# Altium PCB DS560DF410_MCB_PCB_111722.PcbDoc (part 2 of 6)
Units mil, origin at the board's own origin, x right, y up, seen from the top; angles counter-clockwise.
Board outline 5500 x 5000 mil, 6 copper layers (Top Layer, L2_GND1, L3_SIG1, L4_PWR1, L5_GND2, Bottom Layer), stack 61.748 mil thick; 297 components, 231 nets, 1236 pads, 998 vias.
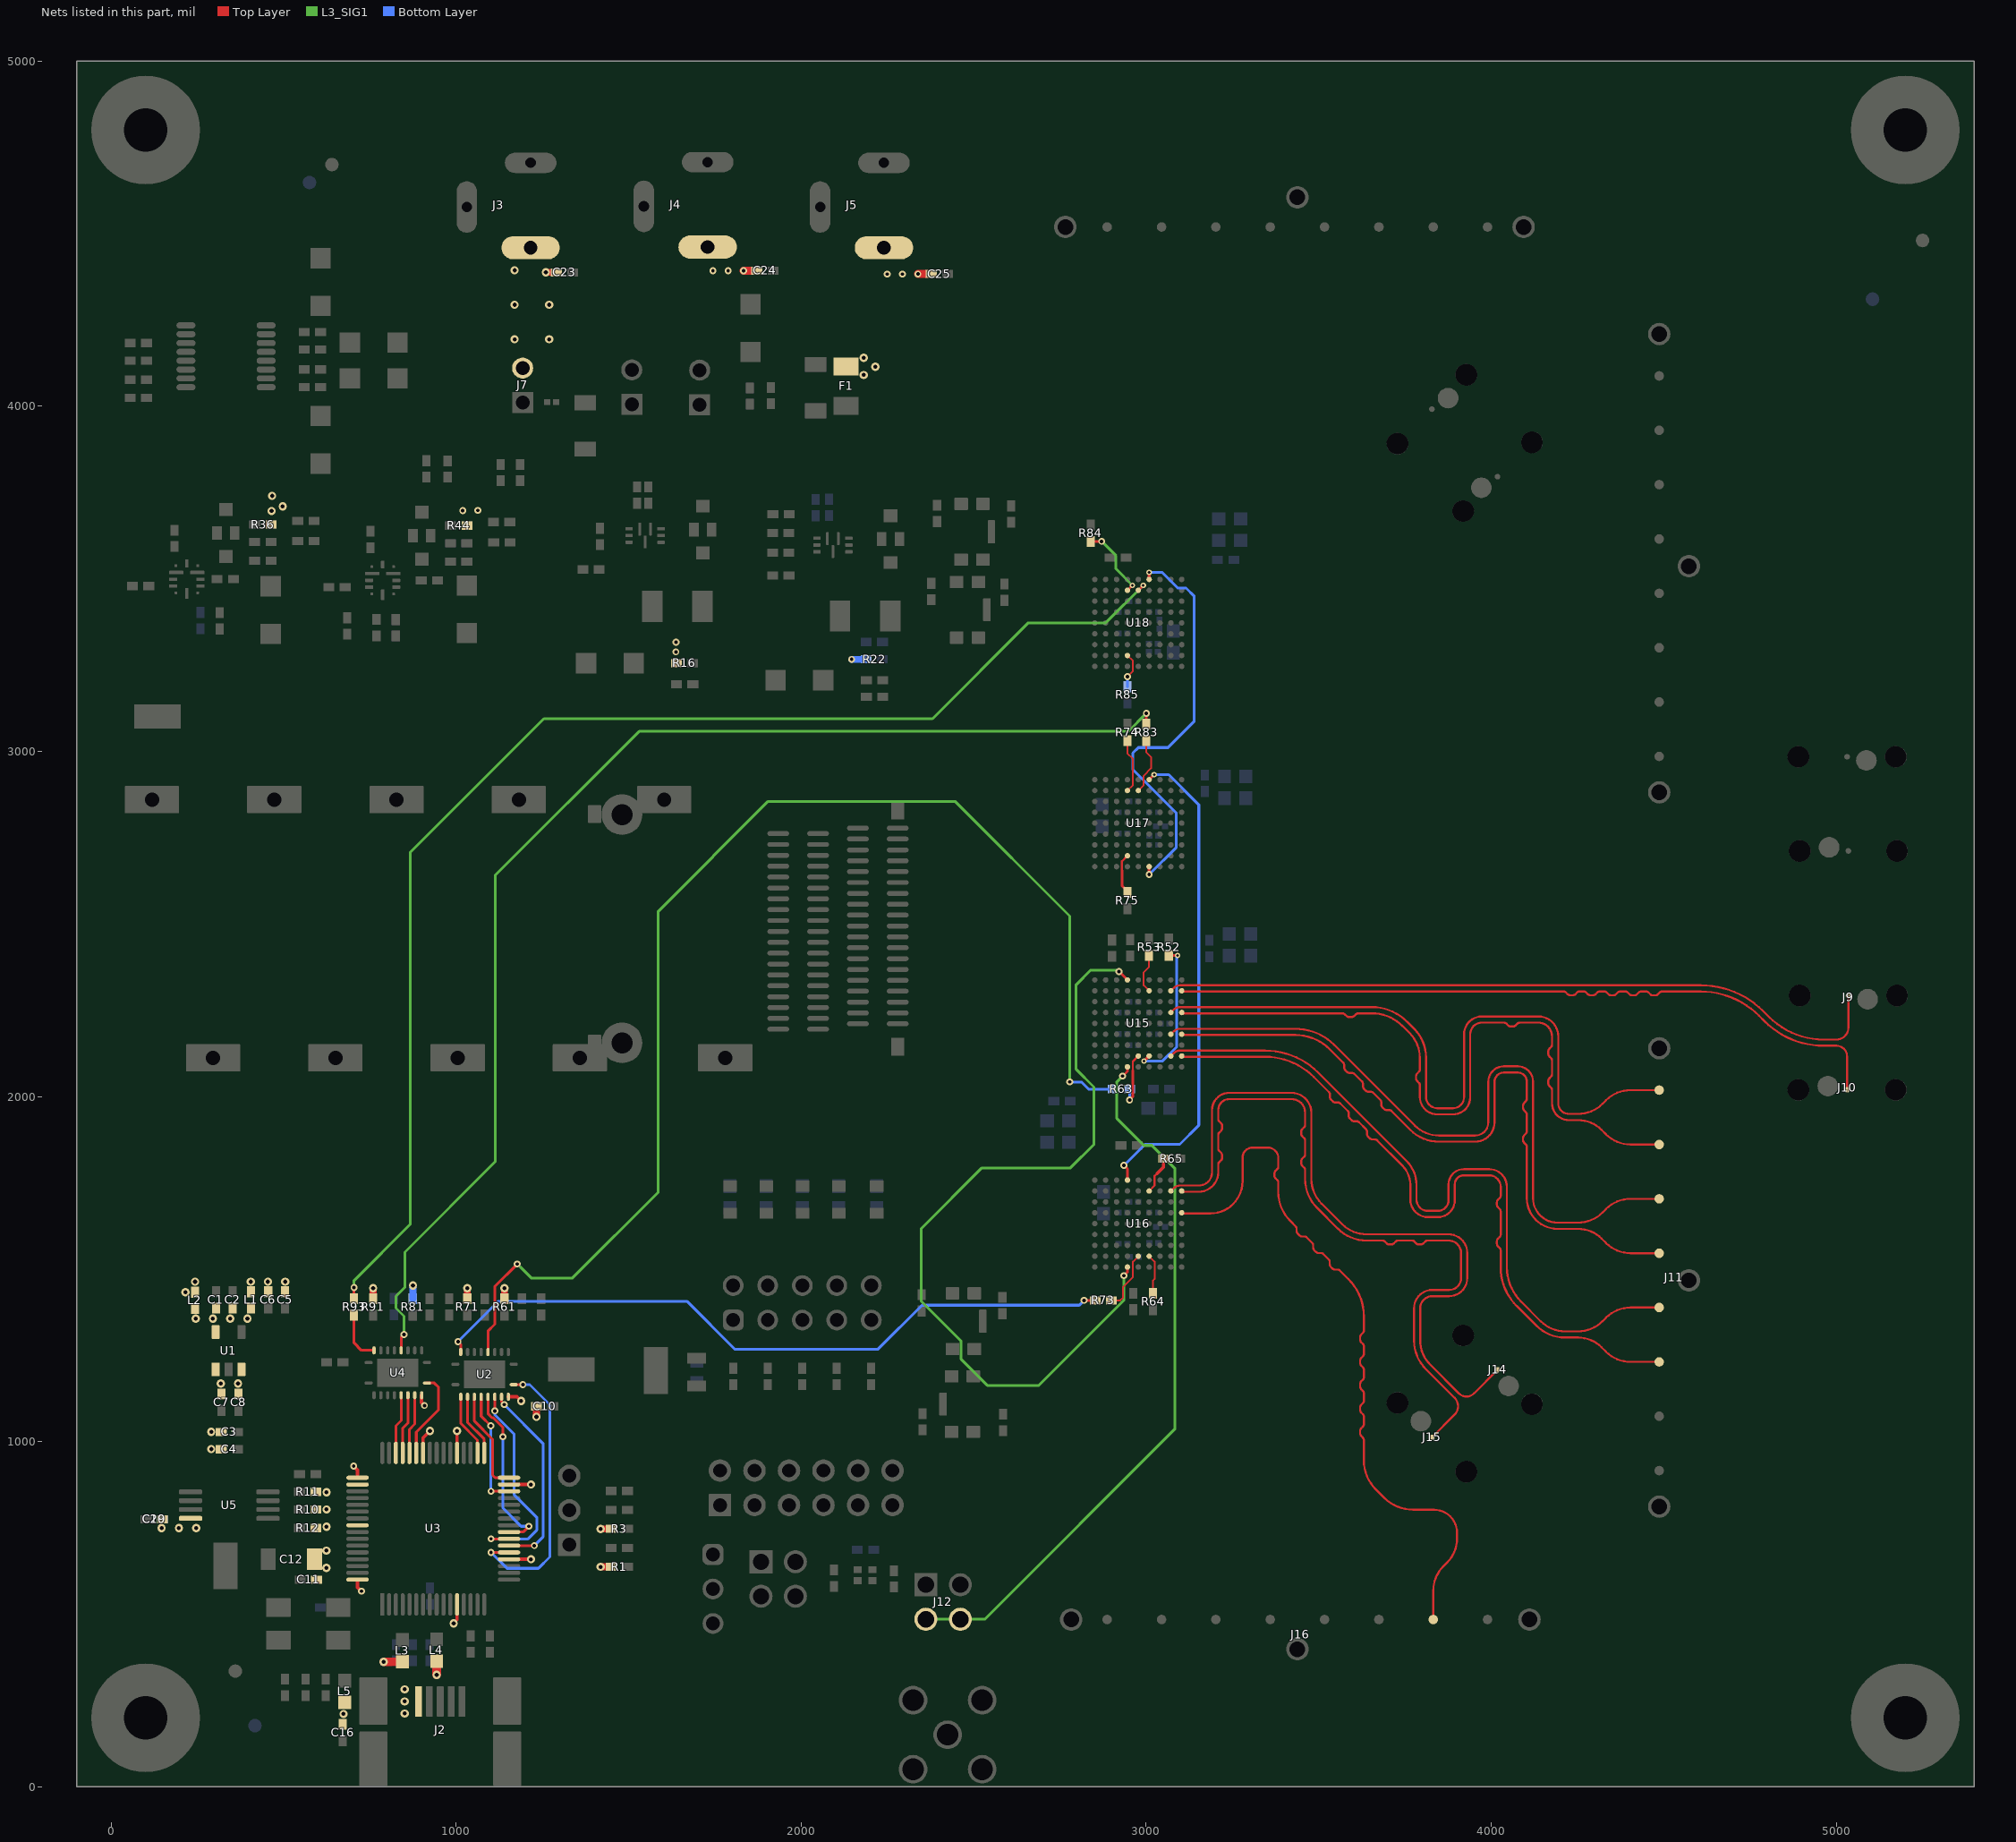
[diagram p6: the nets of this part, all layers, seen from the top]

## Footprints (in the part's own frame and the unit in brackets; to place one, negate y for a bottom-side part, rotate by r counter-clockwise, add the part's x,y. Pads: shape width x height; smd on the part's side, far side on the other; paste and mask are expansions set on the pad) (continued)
SAMTEC_SMA-J-P-H-ST-TH1 [mm] "TH, 5-Leads, Body 7x7mm"
  round 2.1 hole 1.6: 1(0,0) 2(-2.54,2.54) 3(2.54,2.54) 4(2.54,-2.54) 5(-2.54,-2.54)
  silkscreen extent -3.5,-3.5 3.5,3.5, body extent -3.5,-3.5 3.5,3.5, height 9.55
Samtec_TSW-103-08-x-S [mm] "Header, 2.54mm, 3x1, TH"
  rrect50% 1.53x1.53 hole 1.02: 1(-2.54,0)
  round 1.53 hole 1.02: 2(0,0) 3(2.54,0)
  body extent -3.94,-1.27 3.81,1.27, height 8.38
SAMTEC_TSW-105-08-X-D [mm] "Header, 2.54mm, 5x2, TH"
  rrect50% 1.53x1.53 hole 1.02: 1(-1.27,5.08)
  round 1.53 hole 1.02: 2(1.27,5.08) 3(-1.27,2.54) 4(1.27,2.54) 5(-1.27,0) 6(1.27,0) 7(-1.27,-2.54) 8(1.27,-2.54) 9(-1.27,-5.08) 10(1.27,-5.08)
  silkscreen extent -2.54,-6.35 2.54,7.59, body extent -2.54,-6.35 2.54,6.35, height 8.38
SPC02SYAN [mil] "SULLINS"
  round 1 on Mech3: 0(0,0)
  body extent -98,-47 99,47, height 366
Sullins_PxC02DAAN [mm] "Header, 2.54mm, 2x2, TH"
  rect 1.7x1.7 hole 1.2: 1(-1.27,1.27)
  round 1.7 hole 1.2: 2(1.27,1.27) 3(-1.27,-1.27) 4(1.27,-1.27)
  silkscreen extent -2.61,-2.8 2.61,3.2, body extent -2.61,-2.8 2.61,2.8, height 8.58
SW_KMR211GLFS [mm] "SMD. 5-Leads. Body 4.2x2.8mm"
  rrect11% 0.9x1 smd: 1(-2.05,0.8) 2(2.05,0.8) 3(-2.05,-0.8) 4(2.05,-0.8)
  rrect18% 1.7x0.55 smd: 5(0,-1.425)
  silkscreen extent -1.3,1.4 1.3,1.7, body extent -2.3,-1.4 2.3,1.4, height 1.92
Testpoint_Keystone_Miniature [mil] "Miniature SMT test point"
  rect 135x70 smd: 1(0,0)
  silkscreen extent -78,-46 78,45, body extent -52,-20 52,20, height 61
TSSOP-8 [mm] "TSSOP, 8-Leads, Body 3.1x4.5mm (max), Pitch 0.65mm, IPC Medium Density"
  rrect50% 1.7x0.35 smd: 1(-2.85,0.975) 2(-2.85,0.325) 3(-2.85,-0.325) 4(-2.85,-0.975) 5(2.85,-0.975) 6(2.85,-0.325) 7(2.85,0.325) 8(2.85,0.975)
  silkscreen extent -2.98,-1.55 1.6,1.82, body extent -3.2,-1.55 3.2,1.55, height 1.07
TSW-106-07-G-D [mm] "Samtec 100mil, 2x6, 230 mil above insulator"
  rrect6% 1.65x1.65 hole 1.016: 1(-6.35,-1.27)
  round 1.65 hole 1.016: 2(-6.35,1.27) 3(-3.81,-1.27) 4(-3.81,1.27) 5(-1.27,-1.27) 6(-1.27,1.27) 7(1.27,-1.27) 8(1.27,1.27) 9(3.81,-1.27) 10(3.81,1.27) 11(6.35,-1.27) 12(6.35,1.27)
  silkscreen extent -8.64,-2.54 7.62,2.54, body extent -7.62,-2.54 7.62,2.54, height 8.38
WEEE_Minimum [mil] "WEEElie bin"
  silkscreen extent -95,-172 99,104

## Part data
C1 C3 C5 C7 C18: library part CMP-0006268-2, "CAP, CERM, 4.7 uF, 10 V, +/- 10%, X5R, 0402", Cap_Case=0402_065, Manufacturer=TDK, Supplier Part Number 1=445-13820-1-ND, TempCo=X5R, Tolerance_%=10%, Value1="0.003417 ohm", Value2=10V, ValueDisplayed=4.7uF
C2 C4 C6 C8 C9 C10 C13 C17 C19 C20 C53: library part CMP-0860188-1, "CAP, CERM, 0.1 µF, 16 V,+/- 10%, X7R, 0402", Cap_Case=0402, Manufacturer="Taiyo Yuden", TempCo=X7R, Tolerance_%=10%, Value2=16V, ValueDisplayed=0.1µF
C11 C30 C32 C33 C36 C37 C40 C41 C45 C46: library part CMP-0084009-1, "CAP, CERM, 10 µF, 10 V,+/- 20%, X5R, 0402", Cap_Case=0402, Manufacturer="Samsung Electro-Mechanics", Supplier Part Number 1=1276-6830-6-ND, TempCo=X5R, Tolerance_%=20%, Value1="0.001 ohm", Value2=10V, ValueDisplayed=10µF
C12 C27: library part CMP-0008649-2, "CAP, CERM, 100 uF, 10 V, +/- 20%, X5R, 1206_190", Cap_Case=1206_190, Manufacturer=TDK, Supplier Part Number 1=445-6007-1-ND, TempCo=X5R, Tolerance_%=20%, Value1="0.002838 ohm", Value2=10V, ValueDisplayed=100uF
C14 C15: library part CMP-0006439-2, "CAP, CERM, 22 pF, 50 V, +/- 5%, C0G/NP0, 0402", Cap_Case=0402, Manufacturer=MuRata, Supplier Part Number 1=81-GRM1555C1H220JA1D, TempCo=C0G/NP0, Tolerance_%=5%, Value1=Unknown, Value2=50V, ValueDisplayed=22pF
C16: library part CMP-0006590-2, "CAP, CERM, 0.01 uF, 16 V, +/- 10%, X5R, 0402", Cap_Case=0402, Manufacturer=MuRata, Supplier Part Number 1=GRM155R61C103KA01D-ND, TempCo=X5R, Tolerance_%=10%, Value1=Unknown, Value2=16V, ValueDisplayed=0.01uF
C21 C22: library part CMP-0006365-2, "CAP, CERM, 27 pF, 50 V, +/- 5%, C0G/NP0, 0402", Cap_Case=0402, Manufacturer=MuRata, TempCo=C0G/NP0, Tolerance_%=5%, Value1=Unknown, Value2=50V, ValueDisplayed=27pF
C23 C24 C25 C42 C47: library part CMP-0006347-2, "CAP, CERM, 1 uF, 16 V, +/- 10%, X5R, 0402", Cap_Case=0402, Manufacturer="Taiyo Yuden", Supplier Part Number 1=587-3709-2-ND, TempCo=X5R, Tolerance_%=10%, Value1=Unknown, Value2=16V, ValueDisplayed=1uF
C26: library part CMP-0009013-2, "CAP, CERM, 47 uF, 10 V, +/- 10%, X5R, AEC-Q200 Grade 1, 1206", Cap_Case=1206, Manufacturer=MuRata, Supplier Part Number 1=490-12438-1-ND, TempCo=X5R, Tolerance_%=10%, Value1=Unknown, Value2=10V, ValueDisplayed=47uF
C28 C29 C34 C35 C38 C39: library part CMP-0006545-2, "CAP, CERM, 22 uF, 6.3 V, +/- 20%, X5R, 0402", Cap_Case=0402, Manufacturer=MuRata, TempCo=X5R, Tolerance_%=20%, Value1=Unknown, Value2=6.3V, ValueDisplayed=22uF
C31: library part CMP-0008932-2, "CAP, CERM, 220 uF, 4 V, +/- 20%, X5R, 1206_190", Cap_Case=1206, Manufacturer=MuRata, Supplier Part Number 1=490-9774-1-ND, TempCo=X5R, Tolerance_%=20%, Value1=Unknown, Value2=4V, ValueDisplayed=220uF
C43 C44 C48 C49: library part CMP-0006659-2, "CAP, CERM, 0.1 uF, 25 V, +/- 10%, X7R, 0402", Cap_Case=0402, Manufacturer=MuRata, Supplier Part Number 1=490-10698-1-ND, TempCo=X7R, Tolerance_%=10%, Value1=Unknown, Value2=25V, ValueDisplayed=0.1uF
C50 C51 C52 C56 C60 C62 C63 C64 C67 C71 C73 C74 C75 C78 C82 C84 C85 C86 C89 C93: library part CMP-0009670-3, "CAP, CERM, 0.1 uF, 16 V, +/- 10%, X5R, 0201", Cap_Case=0201, Manufacturer=MuRata, Supplier Part Number 1=490-10387-1-ND, TempCo=X5R, Tolerance_%=10%, Value1=Unknown, Value2=16V, ValueDisplayed=0.1uF
C54 C59 C65 C70 C76 C81 C87 C92: library part CMP-0086060-1, "CAP, CERM, 0.01 µF, 25 V,+/- 10%, X5R, 0201", Cap_Case=0201, Manufacturer=MuRata, TempCo=X5R, Tolerance_%=10%, Value2=25V, ValueDisplayed=0.01µF
C55 C66 C77 C88: library part CMP-0860563-1, "CAP, CERM, 0.22 µF, 16 V,+/- 10%, X7R, 0402", Cap_Case=0402, Manufacturer="Samsung Electro-Mechanics", TempCo=X7R, Tolerance_%=10%, Value2=16V, ValueDisplayed=0.22µF
C57 C58 C61 C68 C69 C72 C79 C80 C83 C90 C91 C94: library part CMP-0007335-5, "CAP, CERM, 1 uF, 16 V, +/- 10%, X5R, 0603", Cap_Case=0603, Manufacturer=MuRata, Supplier Part Number 1=490-1536-1-ND, TempCo=X5R, Tolerance_%=10%, Value1=Unknown, Value2=16V, ValueDisplayed=1uF
C95: library part CMP-0086228-1, "CAP, CERM, 10 µF, 16 V,+/- 10%, X5R, 0805", Cap_Case=0805, Manufacturer=MuRata, Supplier Part Number 1=490-6473-1-ND, TempCo=X5R, Tolerance_%=10%, Value2=16V, ValueDisplayed=10µF
C96: library part CMP-0007157-5, "CAP, CERM, 1 uF, 16 V, +/- 10%, X5R, 0603", Cap_Case=0603, Manufacturer=MuRata, Supplier Part Number 1=490-3894-1-ND, TempCo=X5R, Tolerance_%=10%, Value1=Unknown, Value2=16V, ValueDisplayed=1uF
D1 D2 D3 D4 D5 D6 D7 D8 D9: library part CMP-0002920-2, "LED, Green, SMD", Color=Green, Manufacturer=LiteOn, Value1=W, Value2=2V
D10 D11 D12 D13 D14: library part CMP-0002971-3, "LED, Green, SMD", Color=Green, Manufacturer=OSRAM, Value1=W, Value2=1.8V
F1: library part CMP-0003460-2, "Fuse, 8 A, 32VAC/VDC, SMD", Irating_A=8A, Manufacturer=Littelfuse, Supplier Part Number 1=F1610CT-ND
FID1 FID2 FID3 FID4 FID5 FID6: library part CMP-0077181-1, "Fiducial mark.  There is nothing to buy or mount.", Manufacturer=N/A
H1 H2 H3 H4: library part CMP-0003617-1, "Machine Screw, Round, #4-40 x 1/4, Nylon, Philips panhead", Manufacturer="B&F Fastener Supply", Supplier Part Number 1=H542-ND
J1: library part CMP-0075484-1, "Header, 100mil, 3x1, Gold, TH", Manufacturer=Samtec, Supplier Part Number 1=HTSW-103-07-G-S-ND
J2: library part CMP-0079047-2, "Receptacle, USB Mini-AB, 0.8mm, 5x1, Gold, R/A, SMT", Current_A=1A, Manufacturer=Molex, Voltage_V=30V
J3 J4 J5: library part CMP-0074931-1, "Power Jack, mini, 2.5mm OD, R/A, TH", Manufacturer=Switchcraft, Supplier Part Number 1=SC237-ND
J6 J7 J8: library part CMP-0075626-1, "Header, 100mil, 2x1, Gold, TH", Color=Black, Manufacturer=Samtec
J9 J10 J14 J15 J17 J18 J20 J21: library part CMP-0097248-1, "2.92MM JACK,PCB,COMPRESSION W/SL", Dielectric Material=PTFE, Digikey Part Number=900-0732520161-ND, Manufacturer=Molex, Mouser Part Number=538-73252-0161, Operating Temperature Range=to
J11 J16 J19 J22: library part CMP-0074975-1, "Straight PCB plug Pin-in-hole/SMT", Manufacturer=Huber+Suhner
J12 J25: library part CMP-0054598-1, "Header, 2.54mm, 2x2, Gold, TH", Color=Black, Current_A=3A, Manufacturer="Sullins Connector Solutions", Supplier Part Number 1=S2011E-02-ND, Voltage_V=1.8kV
J13: library part CMP-0075495-1, "SMA Jack, Straight, 50 Ohm, Gold, TH", Manufacturer=Samtec, Supplier Part Number 1=SMA-J-P-H-ST-TH1-ND
J23: library part CMP-0086993-2, "76 Position QSFP-DD (Double Density) Receptacle Connector Solder Surface Mount, Right Angle", Current_A=1A, Manufacturer=Molex, Voltage_V=30V
J24: library part CMP-0079327-1, "Header, 2.54mm, 3x1, Gold, TH", Color=Black, Manufacturer=Samtec, Supplier Part Number 1=SAM1038-03-ND
J26: library part CMP-0860034-1, "Header, 2.54mm, 5x2, Gold, TH", Color=Black, Manufacturer=Samtec
J27: library part CMP-0088065-1, "Position QSFP-DD (Double Density) Cage with Heat Sink Connector Press-Fit Through Hole, Right Angle", Manufacturer=Molex
J28: library part CMP-0075412-2, "Header, 100mil, 6x2, Gold, TH", Color=Black, Current_A=6.3A, Manufacturer=Samtec, Supplier Part Number 1=SAM1028-06-ND, Voltage_V=550V
L1 L2: library part CMP-0003317-1, "Ferrite Bead, 600 ohm @ 100 MHz, 0.5 A, 0402", Manufacturer=MuRata, Supplier Part Number 1=490-5441-1-ND, Value1="0.34 ohm", Value2=0.5A, ValueDisplayed="600 ohm"
L3 L4: library part CMP-0003192-2, "Ferrite Bead, 300 ohm @ 100 MHz, 2 A, 0603", Manufacturer="Wurth Elektronik", Supplier Part Number 1=732-1592-1-ND, Value1="0.15 ohm", Value2=2A, ValueDisplayed="300 ohm"
L5: library part CMP-0003185-2, "Ferrite Bead, 180 ohm @ 100 MHz, 0.5 A, 0603", Manufacturer="Wurth Elektronik", Supplier Part Number 1=732-1580-1-ND, Value1="0.3 ohm", Value2=0.5A, ValueDisplayed="180 ohm"
L6 L7: library part CMP-0059748-1, "FIXED IND 220NH 7.7A 8 MOHM SMD", Manufacturer="Würth Elektronik", Value1="0.009 ohm", Value2=7.6A, ValueDisplayed=220nH
LBL1: library part CMP-0003625-1, "Thermal Transfer Printable Labels, 0.650\" W x 0.200\" H - 10,000 per roll", Manufacturer=Brady, Supplier Part Number 1=97C5133
Logo1: library part CMP-0074844-1
Logo3: library part CMP-0074847-1, "FCC_disclaimer"
Logo4: library part CMP-0074769-1
R1 R3 R61 R71 R81 R91: library part CMP-0026676-1, "RES, 2.00 k, 1%, 0.1 W, AEC-Q200 Grade 0, 0402", Manufacturer=Panasonic, Power_W=100mW, Supplier Part Number 1=P2.00KLCT-ND, TempCo="100 ppm/C", Tolerance_%=1%, Value2=0.1W, Value_Code=2k00, ValueDisplayed=2.00k
R2 R4 R5 R39 R43 R47 R51: library part CMP-0026271-2, "RES, 2.49, 1%, 0.063 W, AEC-Q200 Grade 0, 0402", Manufacturer=Vishay-Dale, Power_W=63mW, Supplier Part Number 1=541-2.49LLCT-ND, TempCo="100 ppm/C", Tolerance_%=1%, Value2=0.063W, Value_Code=2R49, ValueDisplayed=2.49
R6: library part CMP-0025991-3, "RES, 12.1 k, 1%, 0.063 W, AEC-Q200 Grade 0, 0402", Manufacturer=Vishay-Dale, Power_W=63mW, Supplier Part Number 1=541-12.1KLCT-ND, TempCo="100 ppm/C", Tolerance_%=1%, Value2=0.063W, Value_Code=12k1, ValueDisplayed=12.1k
R7: library part CMP-0026700-1, "RES, 4.70 k, 1%, 0.1 W, 0402", Manufacturer=Panasonic, Power_W=100mW, Supplier Part Number 1=P4.70KLCT-ND, TempCo="100 ppm/C", Tolerance_%=1%, Value2=0.1W, Value_Code=4k70, ValueDisplayed=4.70k
R8 R52 R53 R54 R55 R65 R66 R67 R74 R76 R77 R86 R87: library part CMP-0026071-3, "RES, 1.00 k, 1%, 0.063 W, AEC-Q200 Grade 0, 0402", Manufacturer=Vishay-Dale, Power_W=63mW, Supplier Part Number 1=541-1.00KLCT-ND, TempCo="100 ppm/C", Tolerance_%=1%, Value2=0.063W, Value_Code=1k00, ValueDisplayed=1.00k
R9 R10 R11 R12: library part CMP-0026796-1, "RES, 10.0 k, 0.1%, 0.063 W, 0402", Manufacturer="TT Electronics/IRC", Power_W=63mW, TempCo="10 ppm/C", Tolerance_%=0.1%, Value2=0.063W, Value_Code=10k0, ValueDisplayed=10.0k
R13: library part CMP-0074667-1, "RES, 2.20 k, 0.1%, 0.0625 W, AEC-Q200 Grade 0, 0402", Manufacturer=Panasonic, Power_W=62.5mW, Supplier Part Number 1=P2.2KDCCT-ND, TempCo="25 ppm/C", Tolerance_%=0.1%, Value2=0.0625W, Value_Code=2k20, ValueDisplayed=2.20k
R14: library part CMP-0027750-1, "RES, 4.70, 1%, 0.05 W, 0201", Manufacturer="Yageo America", Power_W=50mW, Supplier Part Number 1=RC0201FR-074R7L-ND, TempCo="350 ppm/C", Tolerance_%=1%, Value2=0.05W, Value_Code=4R70, ValueDisplayed=4.70
R15 R17 R23 R41 R49: library part CMP-0026716-1, "RES, 1.00 k, 1%, 0.063 W, 0402", Manufacturer=Rohm, Power_W=63mW, Supplier Part Number 1=RHM1.00KLCT-ND, TempCo="100 ppm/C", Tolerance_%=1%, Value2=0.063W, Value_Code=1k00, ValueDisplayed=1.00k
R16 R20 R21 R22 R26 R31 R36 R37 R44 R45 R56 R59 R62 R63 R68 R70 R72 R73 R78 R80 R82 R83 R88 R90 R92 R93: library part CMP-0026992-3, "RES, 0, 5%, 0.1 W, AEC-Q200 Grade 0, 0402", Manufacturer=Panasonic, Power_W=100mW, Supplier Part Number 1=P0.0JCT-ND, TempCo="600 ppm/C", Tolerance_%=5%, Value2=0.1W, Value_Code=0000, ValueDisplayed=0
R18 R24: library part CMP-0026825-5, "RES, 10 k, 5%, 0.063 W, AEC-Q200 Grade 0, 0402", Manufacturer=Vishay-Dale, Power_W=63mW, Supplier Part Number 1=541-10KJCT-ND, TempCo="200 ppm/C", Tolerance_%=5%, Value2=0.063W, Value_Code=10k0, ValueDisplayed=100k
R19 R25: library part CMP-0026825-5, "RES, 10 k, 5%, 0.063 W, AEC-Q200 Grade 0, 0402", Manufacturer=Vishay-Dale, Power_W=63mW, Supplier Part Number 1=541-10KJCT-ND, TempCo="200 ppm/C", Tolerance_%=5%, Value2=0.063W, Value_Code=10k0, ValueDisplayed=56.2k
R27 R29 R32 R34: library part CMP-0026030-3, "RES, 15.0, 1%, 0.063 W, AEC-Q200 Grade 0, 0402", Manufacturer=Vishay-Dale, Power_W=63mW, Supplier Part Number 1=541-15.0LCT-ND, TempCo="100 ppm/C", Tolerance_%=1%, Value2=0.063W, Value_Code=15R0, ValueDisplayed=15.0
R28 R30 R33 R35: library part CMP-0026204-2, "RES, 261, 1%, 0.063 W, AEC-Q200 Grade 0, 0402", Manufacturer=Vishay-Dale, Power_W=63mW, Supplier Part Number 1=541-261LCT-ND, TempCo="100 ppm/C", Tolerance_%=1%, Value2=0.063W, Value_Code=261R, ValueDisplayed=261
R38 R46: library part CMP-0078783-1, "RES, 1.87 k, 1%, 0.063 W, 0402", Manufacturer="Yageo America", Power_W=63mW, Supplier Part Number 1=YAG3048CT-ND, TempCo="100 ppm/C", Tolerance_%=1%, Value2=0.063W, Value_Code=1k87, ValueDisplayed=1.87k
R40 R48: library part CMP-0026383-2, "RES, 44.2 k, 1%, 0.063 W, AEC-Q200 Grade 0, 0402", Manufacturer=Vishay-Dale, Power_W=63mW, Supplier Part Number 1=541-44.2KLCT-ND, TempCo="100 ppm/C", Tolerance_%=1%, Value2=0.063W, Value_Code=44k2, ValueDisplayed=44.2k
R42 R50: library part CMP-0026088-3, "RES, 1.50 k, 1%, 0.063 W, AEC-Q200 Grade 0, 0402", Manufacturer=Vishay-Dale, Power_W=63mW, Supplier Part Number 1=541-1.50KLCT-ND, TempCo="100 ppm/C", Tolerance_%=1%, Value2=0.063W, Value_Code=1k50, ValueDisplayed=1.50k
R57 R69 R79 R89: library part CMP-0025964-3, "RES, 10.2, 1%, 0.063 W, AEC-Q200 Grade 0, 0402", Manufacturer=Vishay-Dale, Power_W=63mW, Supplier Part Number 1=541-10.2LCT-ND, TempCo="100 ppm/C", Tolerance_%=1%, Value2=0.063W, Value_Code=10R2, ValueDisplayed=10.2
R58 R94 R95 R96 R97 R98: library part CMP-0026938-5, "RES, 4.7 k, 5%, 0.063 W, AEC-Q200 Grade 0, 0402", Manufacturer=Vishay-Dale, Power_W=63mW, Supplier Part Number 1=541-4.7KJCT-ND, TempCo="200 ppm/C", Tolerance_%=5%, Value2=0.063W, Value_Code=4k70, ValueDisplayed=4.7k
R60: library part CMP-0026908-3, "RES, 33, 5%, 0.063 W, AEC-Q200 Grade 0, 0402", Manufacturer=Vishay-Dale, PartNumber=CRCW040233R0JNED, Power_W=63mW, Supplier Part Number 1=541-33JCT-ND, TempCo="200 ppm/C", Tolerance_%=5%, Value2=0.063W, Value_Code=33R0, ValueDisplayed=33
R64 R75 R84 R85: library part CMP-0026071-3, "RES, 1.00 k, 1%, 0.063 W, AEC-Q200 Grade 0, 0402", Manufacturer=Vishay-Dale, Power_W=63mW, Supplier Part Number 1=541-1.00KLCT-ND, TempCo="100 ppm/C", Tolerance_%=1%, Value2=0.063W, Value_Code=1k00, ValueDisplayed=20k
R99 R100 R101 R102 R103: library part CMP-0022201-5, "RES, 200, 1%, 0.1 W, AEC-Q200 Grade 0, 0603", Manufacturer=Vishay-Dale, Power_W=100mW, Supplier Part Number 1=541-200HCT-ND, TempCo="100 ppm/C", Tolerance_%=1%, Value2=0.1W, Value_Code=200R, ValueDisplayed=200
S1 S2 S3 S4: library part CMP-0002322-1, "Switch, SPST-NO, Off-Mom, 0.05 A, 32 VDC, SMD", CurrentRating_mA=50A, Manufacturer="C&K Components", Supplier Part Number 1=401-1426-1-ND
SH-J1: library part CMP-0003642-1, "Shunt, 100mil, Flash Gold, Black", Manufacturer="Sullins Connector Solutions", Supplier Part Number 1=S9001-ND
TP1 TP2 TP3 TP4: library part CMP-0055152-2, "Test Point, Miniature, SMT", Manufacturer="Keystone Electronics", Supplier Part Number 1=36-5015TR-ND
U1: library part CMP-0035516-1, "Single Output LDO, 300 mA, Fixed 3.3 V Output, 2 to 5.5 V Input, with Low IQ, 5-pin SOT-23 (DBV), -40 to 125 degC, Green (RoHS & no Sb/Br)", Manufacturer="Texas Instruments"
U2 U4: library part CMP-0074359-2, "8-Bit Bidirectional Voltage-Level Shifter with Auto Direction Sensing and +/-15-kV ESD Protect, RGY0020A (VQFN-20)", Alternate Manufacturer="Texas Instruments"
U3: library part CMP-0086897-1, "IC USB HS QUAD UART/SYNC 64-LQFP", Manufacturer=FTDI
U5: library part CMP-0081524-1, "1K Microwire Compatible Serial EEPROM, TSSOP-8", Manufacturer=Microchip, Supplier Part Number 1=93LC46B-I/ST-ND
U6 U8: library part CMP-0089105-4, "2.4-V to 5.5-V Input, 6-A Step-Down Converter in 1.5-mm x 2.5-mm QFN Package", Manufacturer="Texas Instruments", Max Supply Voltage=5.5V, Min Supply Voltage=2.4V, Nominal Supply Current=4uA, Operating Temperature Range="-40°C to +125°C", Switching Frequency=2.4MHz
U7 U9 U12 U14: library part CMP-0001934-2, "FILTER LC HIGH FREQ 27uF 1206", Manufacturer=MuRata, Supplier Part Number 1=490-6984-1-ND
U10: library part CMP-0066448-2, "4-Bit Dual-Supply Bus Transceiver with Configurable Voltage-Level Shifting and 3-State Outputs, PW0016A (TSSOP-16)", Alternate Manufacturer="Texas Instruments"
U11 U13: library part CMP-0860539-1, "3-A, High-Accuracy (0.75%), Low-Noise (4.4μVRMS), LDO Voltage Regulator, RPS0012A (VQFN-12)", Alternate Manufacturer="Texas Instruments"
U15 U16 U17 U18: library part CMP-0095008-2, "56 Gbps Multi-Rate 4-Channel Retimer with Crosspoint", Manufacturer="Texas Instruments", Max Supply Voltage=1.85V, Min Supply Voltage=1.15V, Operating Temperature Range="-40°C to +110°C"
Y1: library part CMP-0079033-1, "Crystal, 12 MHz, 20 ppm, SMD", Frequency Stability="-20 / +20 ppm", Frequency Tolerance="20 ppm", Frequency_Fixed=12MHz, Manufacturer="Abracon Corporation", Supplier Part Number 1=535-9631-1-ND
Y2: library part SYM-ASCO-25.000MHZ-EK-T3, "XTAL OSC XO 25.0000MHZ CMOS SMD", Frequency Stability=50ppm, Frequency_Fixed=25MHz, Load Capacitance=15pF, Manufacturer="ECS Inc.", Max Supply Current=4.2mA, Max Supply Voltage=3.63V, Min Supply Voltage=2.97V, Operating Temperature Range="-40°C ~ 85°C"
ZZ1: library part CMP-0003616-3
ZZ2: library part CMP-0077236-1
ZZ3: library part CMP-0077237-1
ZZ4 ZZ5: library part CMP-0077238-1

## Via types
v1: diameter 20, hole 10, Top Layer to Bottom Layer, 380 vias
v2: diameter 24, hole 12, Top Layer to Bottom Layer, tented both sides, 226 vias
v3: diameter 20, hole 10, Top Layer to Bottom Layer, tented both sides, 162 vias
v4: diameter 14, hole 8.1, Top Layer to Bottom Layer, tented both sides, 88 vias
v5: diameter 16, hole 8.1, Top Layer to Bottom Layer, tented both sides, 84 vias
v6: diameter 16, hole 8, Top Layer to Bottom Layer, tented both sides, 34 vias
v7: diameter 15, hole 8.1, Top Layer to Bottom Layer, tented both sides, 16 vias
v8: diameter 19.68, hole 7.87, Top Layer to Bottom Layer, tented both sides, 8 vias

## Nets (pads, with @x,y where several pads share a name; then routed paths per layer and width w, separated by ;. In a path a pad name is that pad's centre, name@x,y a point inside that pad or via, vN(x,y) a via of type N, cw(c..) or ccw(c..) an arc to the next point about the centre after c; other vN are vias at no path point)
1P2V_CON: C25.1 J5.1 R16.2 R22.2 | length 80.9
  Top Layer w20: R16.2@1638.37,3255.52 R16.2@1638.6,3255.75 ; C25.1@2376.64,4382.81 C25.1@2377.01,4383.17
  Top Layer w23: v3(2338.45,4382.81) C25.1@2376.64,4382.81
  Bottom Layer w20: v3(2146.43,3266.45) R22.2@2188.28,3266.45
  other v3: 1636.99,3288 1637.37,3316 2249.58,4382.45 2293.54,4382.45
1P8V_CON: C24.1 J4.1 R36.2 R44.2 | length 38.2
  Top Layer w23: v3(1833.19,4392.5) C24.1@1871.38,4392.5
  other v2: 465.25,3696.3 497.36,3709.48 466.8,3740.04
  other v3: 1019.2,3697.12 1062.7,3698.05 1744.32,4392.14 1788.28,4392.14
1P8V_FTDI: C11.1 C12.1 U3.12 U3.37 U3.49 U3.64 | length 199.6
  Top Layer w8: v2(992.9,473.07) 1002.71,482.89 U3.12@1002.71,528.33
  Top Layer w10: v3(703,929.07) 714.33,917.75 U3.49@714.33,895.45 ; U3.64@714.33,600.18 714.33,577.88 v3(725.66,566.55) ; U3.37@1002.71,967.3 v2(1002.71,1030.97)
  other v2: 624.4,634.28 624.4,684.27
3P3V_CON: C23.1 F1.2 J3.1 J7.2 | length 30.6
  Top Layer w20: v2(1260.02,4387.6) C23.1@1290.59,4387.6
  other v2: 2181.2,4090.4 2214.75,4113.85 2181.2,4140.4 1169.59,4193.7 1269.59,4193.7 1169.59,4293.7 1269.59,4293.7 1169.59,4393.7
3P3V_FTDI: C1.1 C2.1 C10.2 C19.1 C20.1 L1.1 L2.1 R1.2 R3.2 R10.2 R11.2 R12.2 R61.2 R71.2 R81.2 R91.2 U1.5 U2.19 U3.20 U3.31 U3.42 U3.50 U3.56 U4.19 U5.8 | length 496.7
  Top Layer w10: U4.19@899.91,1134.47 899.91,1112.86 v3(908.35,1104.43) ; U3.42@904.29,967.3 904.29,1010.97 v2(924.29,1030.97) ; U2.19@1151.35,1129.69 1176.31,1129.69 v2(1188.5,1117.5) ; U3.20@1153.3,659.23 v2(1216.97,659.23) ; U3.31@1153.3,875.77 v2(1216.97,875.77)
  Top Layer w20: R91.2@759.52,1414.04 v2(759.52,1444.6) ; R71.2@1032.4,1414.04 v2(1032.4,1444.6) ; R61.2@1140.1,1414.04 v2(1140.1,1444.6) ; v2(1232.85,1071.74) C10.2@1232.85,1102.3 ; v2(1418.81,637.13) R1.2@1449.38,637.13 ; v2(1418.81,747.13) R3.2@1449.38,747.13
  Bottom Layer w20: R81.2@874.4,1414.04 874.9,1414.53 v2(874.9,1452.15)
  other v2: 146.55,749.75 196.55,749.75 246.55,749.75 624.47,753.57 624.47,803.57 624.47,853.57 245.17,1356.5 295.17,1356.5 345.17,1356.5 395.17,1356.5
3P3V_VPHY: C3.1 C4.1 L2.2 L3.2 | length 54.9
  Top Layer w25: v2(790.03,362.17) L3.2@844.91,362.17
  other v2: 290.45,978.22 290.45,1028.22 215.85,1432.75 243.42,1463.31
3P3V_VPLL: C5.1 C6.1 L1.2 L4.2 | length 39.9
  Top Layer w25: v2(943.66,324.22) L4.2@943.66,364.1
  other v2: 404.66,1463.18 454.66,1463.18 504.65,1463.18
5V_USB: C7.1 C8.1 C16.1 J2.1 L5.1 U1.1 U1.3
  other v2: 673.82,211.03 851.14,212.35 851.14,247.35 851.14,282.35 318.15,1168.22 368.15,1168.22
A4: U2.20 U3.21 | length 824.7
  Top Layer w8: v3(1101.34,678.92) U3.21@1153.3,678.92 ; U2.20@1167.1,1165.12 v3(1193.65,1165.12)
  Bottom Layer w8: v3(1101.34,678.92) 1147.5,632.75 1238.47,632.75 1271.7,665.97 1271.7,1106.7 1213.28,1165.12 v3(1193.65,1165.12)
A5: U2.18 U3.22 | length 564.7
  Top Layer w8: U2.18@1131.67,1129.69 1131.67,1114.86 v3(1139.28,1107.25) ; U3.22@1153.3,698.6 v3(1226.7,698.6)
  Bottom Layer w8: v3(1139.28,1107.25) 1251.9,994.62 1251.9,723.8 v3(1226.7,698.6)
A6: U2.17 U3.23 | length 631.6
  Top Layer w8: v3(1101.34,718.29) U3.23@1153.3,718.29 ; U2.17@1111.98,1129.69 1112.3,1129.37 v3(1112.3,1088.9)
  Bottom Layer w8: v3(1101.34,718.29) 1208.49,718.29 1233.6,743.4 1233.6,781 1167.6,847 1167.6,1022.5 1111.98,1078.12 1112.3,1078.43 v3(1112.3,1088.9)
A7: U2.16 U3.24 | length 504.1
  Top Layer w8: U2.16@1092.3,1129.69 1092.3,1081.18 1104.18,1069.3 1107.73,1069.3 1135.5,1041.53 v3(1135.5,1014.1) ; U3.24@1153.3,737.97 1194.3,737.97 v3(1211.05,754.72)
  Bottom Layer w8: v3(1135.5,1014.1) 1135.5,807.74 1188.52,754.72 v3(1211.05,754.72)
ADDR0_1: R53.1 U15.F8 | length 115.4
  Top Layer w5: R53.1@3008,2408.77 3008,2375.05 2992.75,2359.8 2992.75,2348.2 2992.75,2322 U15.F8@3008.5,2306.25
ADDR0_2: R65.1 U16.F8 | length 110.2
  Top Layer w6: U16.F8@3008.5,1726.13 3024.24,1741.88 3024.24,1769.56 3031.7,1777.02
  Top Layer w9.4: 3031.7,1777.02 3049.78,1795.1 R65.1@3049.78,1819.23
ADDR0_3: R75.1 U17.F8 | length 119
  Top Layer w6: 2929.76,2654.95 2929.76,2681.65 U17.F8@2945.5,2697.39
  Top Layer w8: 2929.76,2654.95 2929.76,2610.79 2945.18,2595.37 R75.1@2945.18,2591.34
ADDR0_4: R85.1 U18.F8 | length 103.6
  Top Layer w5: v3(2945.5,3216.18) 2961.25,3231.92 2961.25,3261.76 U18.F8@2945.5,3277.51
  Bottom Layer w8: R85.1@2945.5,3187 v3(2945.5,3216.18)
ADDR1_1: R52.1 U15.F2 | length 423.5
  Top Layer w8: v6(2994,2102.78) U15.F2@3008.5,2117.28 ; R52.1@3065.5,2408.77 v6(3091,2408.77)
  Bottom Layer w8: v6(2994,2102.78) 3047.58,2102.78 3088.2,2143.4 3088.2,2405.97 v6(3091,2408.77)
ADDR1_2: R64.1 U16.F2 | length 116
  Top Layer w5: U16.F2@3008.5,1537.16 3024.24,1521.41 3024.24,1494.72 3024.24,1471.34 3019.76,1466.86 R64.1@3019.76,1429.51
ADDR1_3: R74.1 U17.F2 | length 158
  Top Layer w5: R74.1@2945.39,3031.31 2945.39,2993.66 2961.25,2977.8 2961.25,2902.12 U17.F2@2945.5,2886.37
ADDR1_4: R84.1 U18.F2 | length 216.5
  Top Layer w8: R84.1@2839,3608.28 v3(2870.78,3608.28) ; U18.F2@2945.5,3466.49 v6(2960,3480.98)
  L3_SIG1 w8: v3(2870.78,3608.28) 2912.32,3566.73 2912.32,3528.66 v6(2960,3480.98)
ALL_DONE_N_1: R63.1 U15.E2 | length 169.7
  Top Layer w6: 2961.25,2074.84 2961.25,2101.53 U15.E2@2977,2117.28
  Top Layer w8: v3(2951.73,1989.8) 2961.25,1999.33 2961.25,2074.84
  Bottom Layer w8: v3(2951.73,1989.8) R63.1@2951.73,2021.58
ALL_DONE_N_1_LS: R63.2 U2.5 | length 3710.3
  Top Layer w8: U2.5@1092.3,1259.61 1092.3,1320.23 1112.3,1340.23 1112.3,1449.7 v3(1177.3,1514.7)
  L3_SIG1 w8: v3(1177.3,1514.7) 1217.9,1474.1 1337.1,1474.1 1585.8,1722.8 1585.8,2536.6 1904.2,2854.99 2446.2,2854.99 2778.4,2522.79 v3(2778.4,2042.08)
  Bottom Layer w8: v3(2778.4,2042.08) 2812.15,2042.08 2833.26,2020.97 2903.87,2020.97 R63.2@2904.48,2021.58
ALL_DONE_N_2: R73.1 U16.E2 | length 175
  Top Layer w5: R73.1@2899.1,1409.25 2924.41,1409.25 2932.96,1417.8 2932.96,1448.46 2961.25,1476.75 2961.25,1494.72 2961.25,1521.41 U16.E2@2977,1537.16
ALL_DONE_N_2_LS: R73.2 U2.9 | length 2043.9
  Top Layer w8: v3(1005.62,1289.7) 1013.56,1281.77 U2.9@1013.56,1259.61 ; v3(2820.08,1409.25) R73.2@2851.85,1409.25
  Bottom Layer w8: v3(1005.62,1289.7) 1122.47,1406.55 1668.85,1406.55 1807.43,1267.97 2223.1,1267.97 2350.38,1395.25 2806.08,1395.25 v3(2820.08,1409.25)
ALL_DONE_N_3: R83.1 U17.E2 | length 165.8
  Top Layer w5: U17.E2@2977,2886.37 2992.75,2902.12 2992.75,2929.18 3014.1,2950.53 3014.1,2983.15 3000.52,2996.73 R83.1@3000.52,3031.18
ALL_DONE_N_3_LS: R83.2 U4.5 | length 3621.9
  Top Layer w8: U4.5@840.86,1264.39 840.86,1302.41 v3(848.93,1310.47) ; R83.2@3000.52,3078.42 v3(3000.52,3110.2)
  L3_SIG1 w8: v3(848.93,1310.47) 848.93,1363.6 825.55,1386.98 825.55,1420.85 851.44,1446.74 851.44,1548.84 1113.2,1810.6 1113.2,2640.4 1530.6,3057.8 2948.13,3057.8 v3(3000.52,3110.2)
ALL_DONE_N_4: R93.1 U18.E2 | length 3826.1
  Top Layer w8: R93.1@704.1,1414.04 v3(704.1,1446.32) ; U18.E2@2977,3466.49 v6(2991.49,3480.98)
  L3_SIG1 w8: v3(704.1,1446.32) 704.1,1466.69 867.2,1629.79 867.2,2707.3 1254.4,3094.5 2380.8,3094.5 2658.42,3372.12 2882.63,3372.12 v6(2991.49,3480.98)
ALL_DONE_N_4_LS: R93.2 U4.9 | length 147.8
  Top Layer w8: R93.2@704.1,1366.79 704.1,1285.9 725.61,1264.39 U4.9@762.12,1264.39
B4: U2.15 U3.30 | length 337.5
  Top Layer w8: U2.15@1072.61,1129.69 1072.61,1073.65 v3(1100.5,1045.77) ; v3(1101.34,856.08) U3.30@1153.3,856.08
  Bottom Layer w8: v3(1100.5,1045.77) 1100.5,856.92 v3(1101.34,856.08)
B5: U2.14 U3.32 | length 299.4
  Top Layer w8: U2.14@1052.93,1129.69 1052.93,1059.57 1105.9,1006.6 1105.9,902.64 1113.09,895.45 U3.32@1153.3,895.45
B6: U2.13 U3.33 | length 182.4
  Top Layer w8: U2.13@1033.24,1129.69 1033.24,1055.36 1081.45,1007.15 U3.33@1081.45,967.3
B7: U2.12 U3.34 | length 182.4
  Top Layer w8: U2.12@1013.56,1129.69 1013.56,1052.64 1061.77,1004.43 U3.34@1061.77,967.3
C4: U3.43 U4.20 | length 255.7
  Top Layer w8: U3.43@884.6,967.3 884.6,1027.8 949.3,1092.5 949.3,1157.43 936.83,1169.9 U4.20@915.66,1169.9
C5: U3.44 U4.18 | length 173.5
  Top Layer w8: U3.44@864.92,967.3 864.92,1035.52 880.23,1050.83 U4.18@880.23,1134.47
C6: U3.45 U4.17 | length 173.5
  Top Layer w8: U3.45@845.23,967.3 845.23,1038.83 860.54,1054.14 U4.17@860.54,1134.47
C7: U3.46 U4.16 | length 173.8
  Top Layer w8: U3.46@825.55,967.3 825.55,1045.77 841.17,1061.39 841.17,1134.15 U4.16@840.86,1134.47
CAL_CLK_IN: J12.3 J12.4 U15.D1 | length 2095.4
  Top Layer w8: v3(2931.55,2058.9) 2945.5,2072.85 U15.D1@2945.5,2085.78
  L3_SIG1 w8: J12.3@2361.39,485.3 J12.4@2461.39,485.3 2532.1,485.3 3082.77,1035.97 3082.77,1792 3016.65,1858.12 2992.93,1858.12 2914.9,1936.15 2914.9,2042.25 v3(2931.55,2058.9)
CAL_CLK_OUT_1: U15.D9 U16.D1 | length 2395.3
  Top Layer w8: v3(2921.15,2362.1) U15.D9@2945.5,2337.75 ; v3(2935.4,1480.75) 2945.5,1490.85 U16.D1@2945.5,1505.66
  L3_SIG1 w8: v3(2921.15,2362.1) 2917.07,2366.18 2839.48,2366.18 2796.93,2323.63 2796.93,2078.65 2848.4,2027.18 2848.4,1860.8 2780.62,1793.02 2523.85,1793.02 2348.43,1617.6 2348.43,1406.28 2463.73,1290.97 2463.73,1238.65 2539.5,1162.88 2689.02,1162.88 2935.4,1409.25 v3(2935.4,1480.75)
CAL_CLK_OUT_2: U16.D9 U17.D1 | length 1426.5
  Top Layer w8: v3(2935.5,1800.43) 2945.5,1790.43 U16.D9@2945.5,1757.63 ; U17.D1@3008.5,2917.87 v6(3022.99,2932.36)
  Bottom Layer w8: v3(2935.5,1800.43) 2996.55,1861.48 3097.18,1861.48 3152.42,1916.72 3152.42,2845.13 3065.19,2932.36 v6(3022.99,2932.36)
CAL_CLK_OUT_3: U17.D9 U18.D1 | length 1217.9
  Top Layer w8: v3(3008.5,2643.1) U17.D9@3008.5,2665.9 ; U18.D1@3008.5,3497.98 v6(3008.5,3518.48)
  Bottom Layer w8: v3(3008.5,2643.1) 3087.3,2721.9 3087.3,2820.8 2961.25,2946.85 2961.25,2995.03 2977.01,3010.79 3062.99,3010.79 3139.3,3087.09 3139.3,3449.2 3115.31,3473.19 3091.3,3473.19 3046.01,3518.48 v6(3008.5,3518.48)
CON_RX1N: J10.1 U15.J8 | length 2131.2
  Top Layer w6: J10.1@5031.16,2019.47 5031.16,2116.31 ccw(c5000.56,2116.31) 5000.56,2146.9 4963.55,2146.9 cw(c4963.55,2389.91) 4791.72,2218.07 4775.51,2234.29 ccw(c4607.2,2065.98) 4607.2,2304 4494.46,2304 ccw(c4494.46,2295.27) 4488.28,2301.44 4482.37,2295.53 cw(c4476.07,2301.83) 4476.07,2292.92 4467.46,2292.92 cw(c4467.46,2300.85) 4461.85,2295.24 4455.65,2301.44 ccw(c4449.48,2295.27) 4449.48,2304 4434,2304 ccw(c4434,2295.27) 4427.82,2301.44 4421.88,2295.49 cw(c4415.67,2301.7) 4415.67,2292.92 4407.43,2292.92 cw(c4407.43,2301.9) 4401.09,2295.55 4395.2,2301.44 ccw(c4389.02,2295.27) 4389.02,2304 4373,2304 ccw(c4373,2295.27) 4366.82,2301.44 4360.96,2295.58 cw(c4354.55,2301.99) 4354.55,2292.92 4346.43,2292.92 cw(c4346.43,2301.9) 4340.09,2295.55 4334.2,2301.44 ccw(c4328.02,2295.27) 4328.02,2304 4313.48,2304 ccw(c4313.48,2295.27) 4307.3,2301.44 4302.44,2296.58 cw(c4293.6,2305.41) 4293.6,2292.92 4288.37,2292.92 cw(c4288.37,2305.41) 4279.53,2296.58 4274.67,2301.44 ccw(c4268.5,2295.27) 4268.5,2304 4255,2304 ccw(c4255,2295.27) 4248.82,2301.44 4243.96,2296.58 cw(c4235.13,2305.41) 4235.13,2292.92 4229.89,2292.92 cw(c4229.89,2305.41) 4221.06,2296.58 4216.2,2301.44 ccw(c4210.02,2295.27) 4210.02,2304 U15.J8@3108.42,2304 ; U15.J8@3108.42,2304 cw(c3108.42,2311.69) U15.J8@3102.98,2306.25 ccw(c3108.42,2311.69) U15.J8@3108.42,2304
CON_RX1P: J9.1 U15.H8 | length 2125.8
  Top Layer w6: U15.H8@3071.49,2306.25 3079.81,2314.57 cw(c3097.74,2296.64) 3097.74,2322 4607.26,2322 cw(c4607.26,2066.12) 4788.09,2247.16 ; 4788.19,2247.05 4804.42,2230.83 ccw(c4963.58,2389.99) 4963.58,2164.9 5000.56,2164.9 ccw(c5000.56,2199.22) 5034.89,2199.22 J9.1@5034.89,2292.33
CON_RX2N: J11.2 U15.J6 | length 2132.2
  Top Layer w6: J11.2@4486.77,1860.89 4403.39,1860.89 cw(c4403.39,1960.89) 4332.68,1890.18 4319.62,1903.25 ccw(c4251.6,1835.23) 4251.6,1931.42 4225,1931.42 cw(c4225,1980.42) 4176,1980.42 4176,2019.02 ccw(c4167.27,2019.02) 4173.44,2025.2 4168.58,2030.06 cw(c4177.41,2038.89) 4164.92,2038.89 4164.92,2044.13 cw(c4177.41,2044.13) 4168.58,2052.96 4173.44,2057.82 ccw(c4167.27,2064) 4176,2064 4176,2104.65 ccw(c4167.27,2104.65) 4173.44,2110.83 4168.58,2115.69 cw(c4177.41,2124.52) 4164.92,2124.52 4164.92,2129.76 cw(c4177.41,2129.76) 4168.58,2138.59 4173.44,2143.46 ccw(c4167.27,2149.63) 4176,2149.63 4176,2173.86 ccw(c4136,2173.86) 4136,2213.86 4083.34,2213.86 ccw(c4083.34,2202.49) 4075.3,2210.53 4071.21,2206.44 cw(c4062.38,2215.28) 4062.38,2202.78 4057.14,2202.78 cw(c4057.14,2215.28) 4048.31,2206.44 4043.52,2211.22 ccw(c4037.16,2204.86) 4037.16,2213.86 3972.76,2213.86 ccw(c3972.76,2180.1) 3939,2180.1 3939,1997.85 cw(c3889.15,1997.85) 3889.15,1948 3843.79,1948 cw(c3843.79,1998.79) 3793,1998.79 3793,2033 ccw(c3784.27,2033) 3790.44,2039.18 3785.58,2044.04 cw(c3794.41,2052.87) 3781.92,2052.87 3781.92,2058.11 cw(c3794.41,2058.11) 3785.58,2066.94 3790.44,2071.8 ccw(c3784.27,2077.98) 3793,2077.98 3793,2112.58 ccw(c3693,2112.58) 3763.71,2183.29 3742.91,2204.09 ccw(c3653.78,2114.95) 3653.78,2241.01 3616.07,2241.01 ccw(c3616.07,2227.28) 3606.36,2236.99 3602.96,2233.59 cw(c3594.13,2242.42) 3594.13,2229.93 3588.89,2229.93 cw(c3588.89,2242.42) 3580.06,2233.59 3575.94,2237.71 ccw(c3567.97,2229.74) 3567.97,2241.01 U15.J6@3108.42,2241.01 ; U15.J6@3108.42,2241.01 cw(c3108.42,2248.7) U15.J6@3102.98,2243.26 ccw(c3108.42,2248.7) U15.J6@3108.42,2241.01
CON_RX2P: J11.1 U15.H6 | length 2125.4
  Top Layer w6: U15.H6@3071.49,2243.26 3079.81,2251.58 cw(c3097.74,2233.65) 3097.74,2259.01 3653.78,2259.01 cw(c3653.78,2114.95) 3755.64,2216.82 3776.44,2196.01 cw(c3693,2112.58) 3811,2112.58 3811,1998.79 ccw(c3843.79,1998.79) 3843.79,1966 3889.15,1966 ccw(c3889.15,1997.85) 3921,1997.85 3921,2180.1 cw(c3972.76,2180.1) 3972.76,2231.86 4136,2231.86 cw(c4136,2173.86) 4194,2173.86 4194,1980.42 ccw(c4225,1980.42) 4225,1949.42 4251.6,1949.42 ccw(c4251.6,2049.42) 4322.31,1978.71 4332.68,1989.08 cw(c4403.39,1918.37) 4403.39,2018.37 J11.1@4486.77,2018.37
CON_RX3N: J11.4 U15.J4 | length 2132.3
  Top Layer w6: J11.4@4486.77,1545.93 4403.39,1545.93 cw(c4403.39,1645.93) 4332.68,1575.22 4319.62,1588.28 ccw(c4251.6,1520.27) 4251.6,1616.46 4191.68,1616.46 cw(c4191.68,1705.04) 4103.1,1705.04 4103.1,1853.92 ccw(c4094.37,1853.92) 4100.54,1860.1 4095.68,1864.96 cw(c4104.52,1873.79) 4092.02,1873.79 4092.02,1879.03 cw(c4104.52,1879.03) 4095.68,1887.86 4100.18,1892.36 ccw(c4093.13,1899.41) 4103.1,1899.41 4103.1,1947.17 ccw(c4092.56,1947.17) 4100.01,1954.62 4095.68,1958.96 cw(c4104.52,1967.79) 4092.02,1967.79 4092.02,1973.03 cw(c4104.52,1973.03) 4095.68,1981.86 4099.73,1985.92 ccw(c4091.6,1994.04) 4103.1,1994.04 4103.1,2042.7 ccw(c4076.5,2042.7) 4076.5,2069.3 4036.6,2069.3 ccw(c4036.6,2042) 4009.3,2042 4009.3,1925 cw(c3953.2,1925) 3953.2,1868.9 3848.55,1868.9 cw(c3848.55,1986.9) 3765.12,1903.46 3710.7,1957.87 ccw(c3703.97,1951.15) 3703.97,1960.66 3697.42,1960.66 cw(c3697.42,1973.15) 3688.59,1964.32 3684.88,1968.02 cw(c3693.72,1976.86) 3681.22,1976.86 3681.22,1983.1 ccw(c3670.96,1983.1) 3678.22,1990.36 3658.02,2010.55 ccw(c3650.63,2003.16) 3650.63,2013.61 3644.47,2013.61 cw(c3644.47,2026.1) 3635.64,2017.27 3631.93,2020.97 cw(c3640.77,2029.81) 3628.27,2029.81 3628.27,2036.13 ccw(c3618.21,2036.13) 3625.32,2043.25 3603.48,2065.09 ccw(c3596.31,2057.92) 3596.31,2068.06 3590.02,2068.06 cw(c3590.02,2080.55) 3581.19,2071.72 3577.48,2075.42 cw(c3586.32,2084.26) 3573.82,2084.26 3573.82,2090.53 ccw(c3563.63,2090.53) 3570.84,2097.74 3531.65,2136.93 ccw(c3432.45,2037.73) 3432.45,2178.02 U15.J4@3108.42,2178.02 ; U15.J4@3108.42,2178.02 cw(c3108.42,2185.7) U15.J4@3102.98,2180.27 ccw(c3108.42,2185.7) U15.J4@3108.42,2178.02
CON_RX3P: J11.3 U15.H4 | length 2125.6
  Top Layer w6: U15.H4@3071.49,2180.27 3079.81,2188.59 cw(c3097.74,2170.66) 3097.74,2196.02 3432.45,2196.02 cw(c3432.45,2037.73) 3544.37,2149.66 ; 3544.38,2149.65 3777.84,1916.19 ccw(c3848.55,1986.9) 3848.55,1886.9 3953.2,1886.9 ccw(c3953.2,1925) 3991.3,1925 3991.3,2042 cw(c4036.6,2042) 4036.6,2087.3 4076.5,2087.3 cw(c4076.5,2042.7) 4121.1,2042.7 4121.1,1705.04 ccw(c4191.68,1705.04) 4191.68,1634.46 4251.6,1634.46 ccw(c4251.6,1734.46) 4322.31,1663.75 4332.68,1674.12 cw(c4403.39,1603.41) 4403.39,1703.41 J11.3@4486.77,1703.41
CON_RX4N: J11.6 U15.J2 | length 2131.8
  Top Layer w6: J11.6@4486.77,1230.97 4403.39,1230.97 cw(c4403.39,1330.97) 4332.68,1260.26 4319.62,1273.32 ccw(c4251.6,1205.31) 4251.6,1301.5 4213.92,1301.5 cw(c4213.92,1419.5) 4130.49,1336.05 4073.62,1392.93 cw(c4185.44,1504.75) 4027.3,1504.75 4027.3,1554.06 ccw(c4017.79,1554.06) 4024.51,1560.79 4019.88,1565.42 cw(c4028.72,1574.26) 4016.22,1574.26 4016.22,1579.49 cw(c4028.72,1579.49) 4019.88,1588.33 4024.29,1592.74 ccw(c4017.04,1600) 4027.3,1600 4027.3,1667.06 ccw(c4017.79,1667.06) 4024.51,1673.79 4019.88,1678.42 cw(c4028.72,1687.26) 4016.22,1687.26 4016.22,1692.49 cw(c4028.72,1692.49) 4019.88,1701.33 4024.29,1705.74 ccw(c4017.04,1713) 4027.3,1713 4027.3,1737.97 ccw(c3993.77,1737.97) 3993.77,1771.5 3920.5,1771.5 ccw(c3920.5,1745.2) 3894.2,1745.2 3894.2,1699.22 cw(c3845.48,1699.22) 3845.48,1650.5 3815.92,1650.5 cw(c3815.92,1701.02) 3765.4,1701.02 3765.4,1743.37 ccw(c3685.07,1743.37) 3741.87,1800.17 3669.44,1872.61 ccw(c3662.71,1865.88) 3662.71,1875.39 3656.16,1875.39 cw(c3656.16,1887.89) 3647.32,1879.05 3643.62,1882.76 cw(c3652.46,1891.59) 3639.96,1891.59 3639.96,1897.83 ccw(c3629.7,1897.83) 3636.96,1905.09 3616.76,1925.28 ccw(c3609.37,1917.89) 3609.37,1928.34 3603.21,1928.34 cw(c3603.21,1940.84) 3594.37,1932 3590.67,1935.71 cw(c3599.51,1944.54) 3587.01,1944.54 3587.01,1950.86 ccw(c3576.94,1950.86) 3584.06,1957.98 3562.22,1979.82 ccw(c3555.05,1972.65) 3555.05,1982.79 3548.76,1982.79 cw(c3548.76,1995.29) 3539.92,1986.45 3536.22,1990.16 cw(c3545.06,1998.99) 3532.56,1998.99 3532.56,2005.26 ccw(c3522.37,2005.26) 3529.58,2012.47 3485.78,2056.27 ccw(c3343.93,1914.42) 3343.93,2115.02 U15.J2@3108.42,2115.02 ; U15.J2@3108.42,2115.02 cw(c3108.42,2122.71) U15.J2@3102.98,2117.28 ccw(c3108.42,2122.71) U15.J2@3108.42,2115.02
CON_RX4P: J11.5 U15.H2 | length 2125
  Top Layer w6: U15.H2@3071.49,2117.28 3079.81,2125.6 cw(c3097.74,2107.67) 3097.74,2133.02 3343.93,2133.02 cw(c3343.93,1914.42) 3498.49,2069.01 3754.6,1812.9 cw(c3685.07,1743.37) 3783.4,1743.37 3783.4,1701.02 ccw(c3815.92,1701.02) 3815.92,1668.5 3845.48,1668.5 ccw(c3845.48,1699.22) 3876.2,1699.22 3876.2,1745.2 cw(c3920.5,1745.2) 3920.5,1789.5 3993.77,1789.5 cw(c3993.77,1737.97) 4045.3,1737.97 4045.3,1504.75 ccw(c4185.44,1504.75) 4086.34,1405.66 4143.21,1348.79 ccw(c4213.92,1419.5) 4213.92,1319.5 4251.6,1319.5 ccw(c4251.6,1419.5) 4322.31,1348.79 4332.68,1359.16 cw(c4403.39,1288.45) 4403.39,1388.45 J11.5@4486.77,1388.45
CON_RX5N: J15.1 U16.J8 | length 2129.6
  Top Layer w6: J15.1@3827.91,1012.36 3893.75,1078.2 ccw(c3869.48,1102.46) 3893.75,1126.73 3810.56,1209.93 cw(c3894,1293.36) 3776,1293.36 3776,1386.1 cw(c3829.4,1386.1) 3829.4,1439.5 3877.98,1439.5 ccw(c3877.98,1473.92) 3912.4,1473.92 3912.4,1546.3 ccw(c3876.1,1546.3) 3876.1,1582.6 3815.41,1582.6 ccw(c3815.41,1573.87) 3809.24,1580.04 3803.42,1574.23 cw(c3796.89,1580.76) 3796.89,1571.52 3788.39,1571.52 cw(c3788.39,1579.39) 3782.82,1573.83 3776.61,1580.04 ccw(c3770.43,1573.87) 3770.43,1582.6 3729.78,1582.6 ccw(c3729.78,1573.87) 3723.6,1580.04 3717.77,1574.21 cw(c3711.28,1580.7) 3711.28,1571.52 3702.95,1571.52 cw(c3702.95,1579.87) 3697.05,1573.97 3690.98,1580.04 ccw(c3684.8,1573.87) 3684.8,1582.6 3638.62,1582.6 cw(c3638.62,1700.6) 3555.19,1617.16 3495.16,1677.19 cw(c3578.6,1760.62) 3460.6,1760.62 3460.6,1786.89 ccw(c3451.87,1786.89) 3458.04,1793.06 3452.7,1798.41 cw(c3460.36,1806.08) 3449.52,1806.08 3449.52,1813.54 cw(c3458.29,1813.54) 3452.09,1819.74 3458.04,1825.69 ccw(c3451.87,1831.87) 3460.6,1831.87 3460.6,1872.52 ccw(c3451.87,1872.52) 3458.04,1878.7 3452.18,1884.55 cw(c3458.61,1890.98) 3449.52,1890.98 3449.52,1899.62 cw(c3457.22,1899.62) 3451.78,1905.06 3458.04,1911.32 ccw(c3451.87,1917.5) 3460.6,1917.5 3460.6,1953.1 ccw(c3421.3,1953.1) 3421.3,1992.4 3240.6,1992.4 ccw(c3240.6,1960.6) 3208.8,1960.6 3208.8,1934.1 ccw(c3217.53,1934.1) 3211.36,1927.92 3217.57,1921.72 cw(c3211.98,1916.13) 3219.88,1916.13 3219.88,1907.7 cw(c3210.49,1907.7) 3217.14,1901.07 3211.36,1895.3 ccw(c3217.53,1889.12) 3208.8,1889.12 3208.8,1848.47 ccw(c3217.53,1848.47) 3211.36,1842.29 3217.14,1836.51 cw(c3210.54,1829.91) 3219.88,1829.91 3219.88,1821.75 cw(c3211.27,1821.75) 3217.36,1815.66 3211.36,1809.66 ccw(c3217.53,1803.49) 3208.8,1803.49 3208.8,1780.2 cw(c3152.48,1780.2) 3152.48,1723.88 U16.J8@3108.42,1723.88 ; U16.J8@3108.42,1723.88 cw(c3108.42,1731.57) U16.J8@3102.98,1726.13 ccw(c3108.42,1731.57) U16.J8@3108.42,1723.88
CON_RX5P: J14.1 U16.H8 | length 2125.9
  Top Layer w6: U16.H8@3071.49,1726.13 3079.81,1734.45 cw(c3097.74,1716.53) 3097.74,1741.88 3152.48,1741.88 ccw(c3152.48,1780.2) 3190.8,1780.2 3190.8,1960.6 cw(c3240.6,1960.6) 3240.6,2010.4 3421.3,2010.4 cw(c3421.3,1953.1) 3478.6,1953.1 3478.6,1760.62 ccw(c3578.6,1760.62) 3507.89,1689.91 3567.91,1629.89 ccw(c3638.62,1700.6) 3638.62,1600.6 3876.1,1600.6 cw(c3876.1,1546.3) 3930.4,1546.3 3930.4,1473.92 cw(c3877.98,1473.92) 3877.98,1421.5 3829.4,1421.5 ccw(c3829.4,1386.1) 3794,1386.1 3794,1293.36 ccw(c3894,1293.36) 3823.29,1222.65 3906.48,1139.46 ccw(c3928.11,1161.09) 3949.74,1139.46 J14.1@4018.22,1207.94
CON_RX6N: J16.2 U16.J6 | length 2126.2
  Top Layer w6: U16.J6@3102.98,1663.14 ccw(c3108.42,1668.58) 3108.42,1660.89 3185.79,1660.89 ccw(c3185.79,1754.2) 3279.1,1754.2 3279.1,1822.78 cw(c3308,1822.78) 3308,1851.68 3352.58,1851.68 cw(c3352.58,1821.46) 3382.8,1821.46 3382.8,1796.18 cw(c3374.07,1796.18) 3380.24,1790 3375.44,1785.2 ccw(c3384.41,1776.23) 3371.72,1776.24 3371.72,1770.96 ccw(c3383.96,1770.96) 3375.3,1762.31 3380.24,1757.38 cw(c3374.07,1751.2) 3382.8,1751.2 3382.8,1722.87 ccw(c3500.8,1722.87) 3417.36,1639.44 3433.3,1623.5 cw(c3427.12,1617.32) 3435.85,1617.32 3435.85,1610.34 ccw(c3448.09,1610.34) 3439.44,1601.69 3443.16,1597.96 ccw(c3452.13,1606.93) 3452.13,1594.25 3458.93,1594.25 cw(c3458.93,1585.52) 3465.1,1591.69 3481.31,1575.48 cw(c3475.13,1569.31) 3483.87,1569.31 3483.87,1562.33 ccw(c3496.1,1562.33) 3487.45,1553.67 ; 3487.45,1553.68 3491.17,1549.95 ; 3491.18,1549.94 ccw(c3500.14,1558.92) 3500.14,1546.24 3506.94,1546.24 cw(c3506.94,1537.5) 3513.11,1543.68 3529.32,1527.47 cw(c3523.15,1521.3) 3531.88,1521.3 3531.88,1514.31 ccw(c3544.11,1514.31) 3535.46,1505.66 3539.19,1501.94 ccw(c3548.16,1510.91) 3548.16,1498.22 3554.95,1498.22 cw(c3554.95,1489.49) 3561.13,1495.67 3586.1,1470.7 cw(c3478.3,1362.97) 3630.7,1362.97 3630.7,1321.6 cw(c3621.97,1321.6) 3628.14,1315.42 3623.2,1310.49 ccw(c3631.86,1301.84) 3619.62,1301.84 3619.62,1296.57 ccw(c3632.31,1296.57) 3623.34,1287.6 3628.14,1282.8 cw(c3621.97,1276.62) 3630.7,1276.62 3630.7,1253.7 cw(c3621.97,1253.7) 3628.14,1247.52 3623.2,1242.59 ccw(c3631.86,1233.94) 3619.62,1233.94 3619.62,1228.67 ccw(c3632.31,1228.67) 3623.34,1219.7 3628.14,1214.9 cw(c3621.97,1208.72) 3630.7,1208.72 3630.7,1186.16 cw(c3621.1,1186.16) 3627.89,1179.37 3623.2,1174.69 ccw(c3631.86,1166.04) 3619.62,1166.04 3619.62,1160.77 ccw(c3632.31,1160.77) 3623.34,1151.8 3627.22,1147.92 cw(c3618.81,1139.51) 3630.7,1139.51 3630.7,1117.9 cw(c3621.97,1117.9) 3628.14,1111.72 3623.2,1106.79 ccw(c3631.86,1098.14) 3619.62,1098.14 3619.62,1092.87 ccw(c3632.31,1092.87) 3623.34,1083.9 3628.14,1079.09 cw(c3621.97,1072.92) 3630.7,1072.92 3630.7,1051.03 cw(c3619.48,1051.03) 3627.41,1043.1 3623.2,1038.89 ccw(c3631.86,1030.24) 3619.62,1030.24 3619.62,1024.97 ccw(c3632.31,1024.97) 3623.34,1016 3627.48,1011.86 cw(c3619.7,1004.08) 3630.7,1004.08 3630.7,945.32 ccw(c3748.7,945.32) 3665.26,861.89 3689.96,837.19 ccw(c3773.39,920.63) 3773.39,802.63 3834.08,802.63 cw(c3834.08,735.95) 3900.76,735.95 3900.76,719.64 cw(c3800.76,719.64) 3871.47,648.93 3861.09,638.56 ccw(c3931.81,567.85) 3831.81,567.85 J16.2@3831.81,484.47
